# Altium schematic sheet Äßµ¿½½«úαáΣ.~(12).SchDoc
size A4
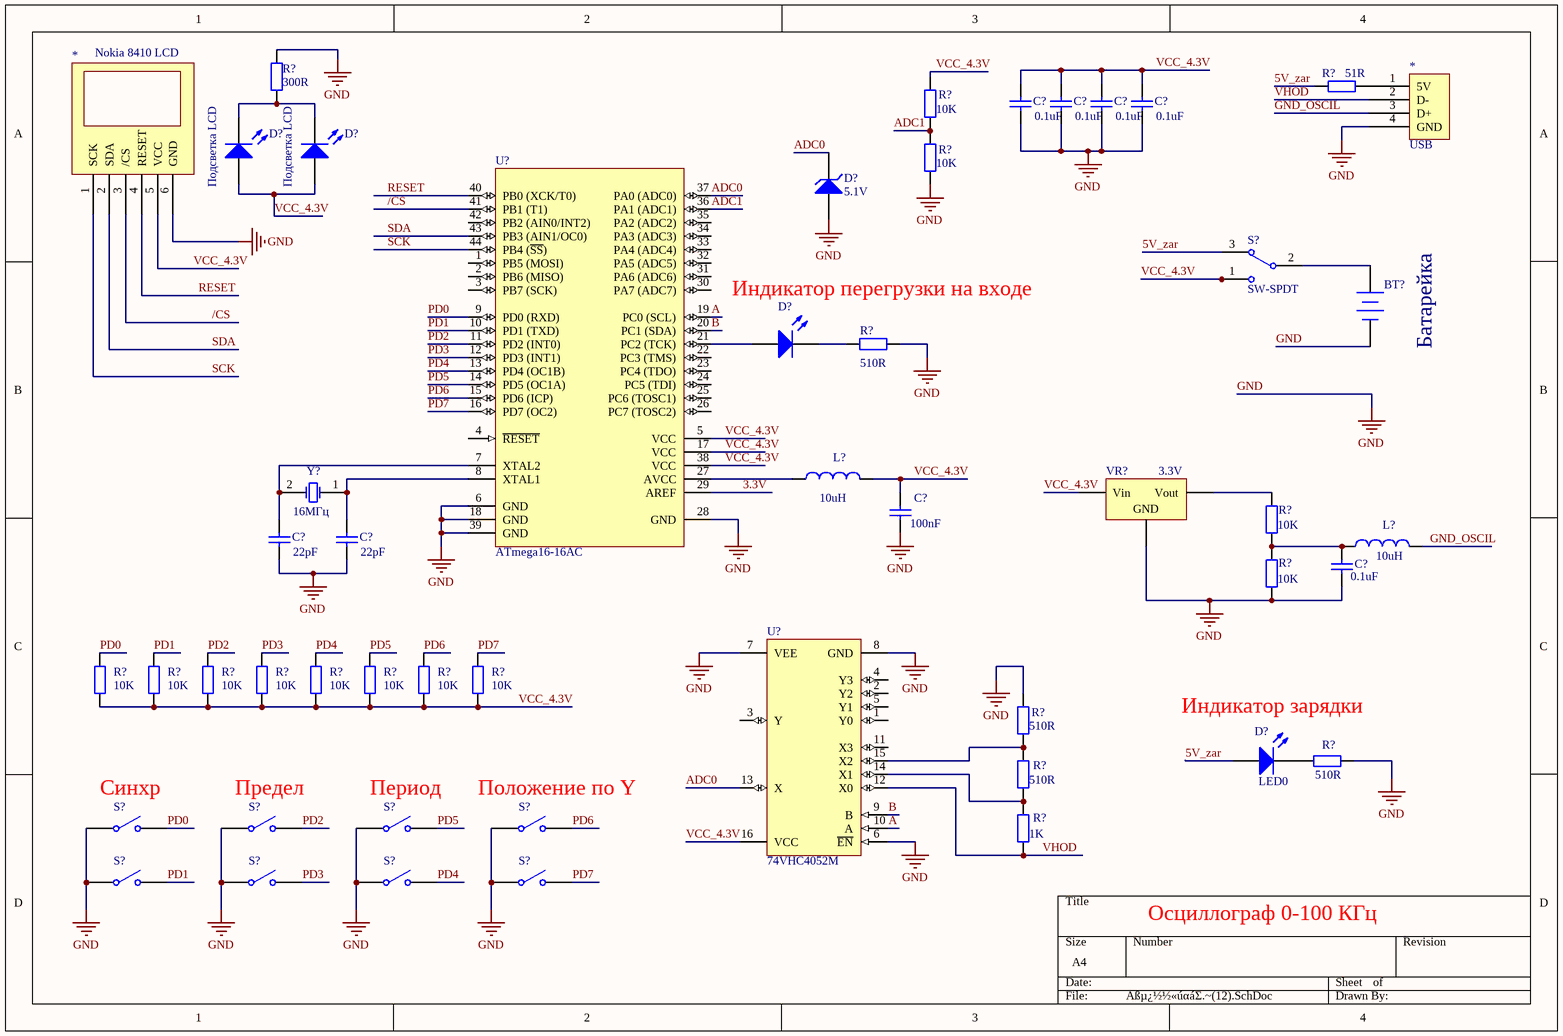
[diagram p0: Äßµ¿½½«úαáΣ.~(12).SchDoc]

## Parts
(Parts that share a designator on the sheet are numbered #1, #2 ... from top to bottom, then left to right.)
*#1  USB
*#2  Nokia 8410 LCD
BT?  Батарейка  [BAT-2]
C?#1  value 0.1uF  [RAD-0.3]  (hidden comment: Cap)
C?#2  value 0.1uF  [RAD-0.3]  (hidden comment: Cap)
C?#3  value 0.1uF  [RAD-0.3]  (hidden comment: Cap)
C?#4  value 0.1uF  [RAD-0.3]  (hidden comment: Cap)
C?#5  value 100nF  [RAD-0.3]  (hidden comment: Cap)
C?#6  value 22pF  [RAD-0.3]  (hidden comment: Cap)
C?#7  value 22pF  [RAD-0.3]  (hidden comment: Cap)
C?#8  value 0.1uF  [RAD-0.3]  (hidden comment: Cap)
D?#1  Подсветка LCD  [LED-0]
D?#2  Подсветка LCD  [LED-0]
D?#3  5.1V  [DIODE-0.7]
D?#4  LED0  [LED-0]  (value not drawn)
D?#5  LED0  [LED-0]
L?#1  value 10uH  [INDC1005AL]  (hidden comment: Inductor)
L?#2  value 10uH  [INDC1005AL]  (hidden comment: Inductor)
R?#1  value 51R  [AXIAL-0.4]  (hidden comment: Res2)
R?#2  value 300R  [AXIAL-0.4]  (hidden comment: Res2)
R?#3  value 10K  [AXIAL-0.4]  (hidden comment: Res2)
R?#4  value 10K  [AXIAL-0.4]  (hidden comment: Res2)
R?#5  value 510R  [AXIAL-0.4]  (hidden comment: Res2)
R?#6  value 10K  [AXIAL-0.4]  (hidden comment: Res2)
R?#7  value 10K  [AXIAL-0.4]  (hidden comment: Res2)
R?#8  value 10K  [AXIAL-0.4]  (hidden comment: Res2)
R?#9  value 10K  [AXIAL-0.4]  (hidden comment: Res2)
R?#10  value 10K  [AXIAL-0.4]  (hidden comment: Res2)
R?#11  value 10K  [AXIAL-0.4]  (hidden comment: Res2)
R?#12  value 10K  [AXIAL-0.4]  (hidden comment: Res2)
R?#13  value 10K  [AXIAL-0.4]  (hidden comment: Res2)
R?#14  value 10K  [AXIAL-0.4]  (hidden comment: Res2)
R?#15  value 10K  [AXIAL-0.4]  (hidden comment: Res2)
R?#16  value 510R  [AXIAL-0.4]  (hidden comment: Res2)
R?#17  value 510R  [AXIAL-0.4]  (hidden comment: Res2)
R?#18  value 510R  [AXIAL-0.4]  (hidden comment: Res2)
R?#19  value 1K  [AXIAL-0.4]  (hidden comment: Res2)
S?#1  SW-SPDT  [TL36WW15050]
S?#2  SW-SPST  [SPST-2]  (value not drawn)
S?#3  SW-SPST  [SPST-2]  (value not drawn)
S?#4  SW-SPST  [SPST-2]  (value not drawn)
S?#5  SW-SPST  [SPST-2]  (value not drawn)
S?#6  SW-SPST  [SPST-2]  (value not drawn)
S?#7  SW-SPST  [SPST-2]  (value not drawn)
S?#8  SW-SPST  [SPST-2]  (value not drawn)
S?#9  SW-SPST  [SPST-2]  (value not drawn)
U?#1  ATmega16-16AC  [44A_N]
U?#2  74VHC4052M  [M16A_N]
VR?  3.3V  [TO254P1510-3_4N]
Y?  16МГц  [BCY-W2/D3.1]

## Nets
GND: *#1.4(GND) *#2.6(GND) BT?.2(-) C?#1.1 C?#2.1 C?#3.1 C?#4.1 C?#5.1 C?#6.1 C?#7.1 C?#8.1 D?#3.1(A) R?#2.2 R?#4.1 R?#5.2 R?#7.2 R?#16.2 R?#17.2 S?#2.1(COMMON) S?#3.1(COMMON) S?#4.1(COMMON) S?#5.1(COMMON) S?#6.1(COMMON) S?#7.1(COMMON) S?#8.1(COMMON) S?#9.1(COMMON) U?#1.6(GND) U?#1.18(GND) U?#1.28(GND) U?#1.39(GND) U?#2.6(~{EN}) U?#2.7(VEE) U?#2.8(GND) VR?.2(GND)
3.3V: U?#1.29(AREF)
5V_zar: D?#5.1(A) R?#1.1 S?#1.3
/CS: *#2.3(/CS) U?#1.41(PB1_(T1))
A: U?#1.19(PC0_(SCL)) U?#2.10(A)
ADC0: D?#3.2(K) U?#1.37(PA0_(ADC0)) U?#2.13(X)
ADC1: R?#3.1 R?#4.2 U?#1.36(PA1_(ADC1))
B: U?#1.20(PC1_(SDA)) U?#2.9(B)
GND_OSCIL: *#1.3(D+) L?#2.2
PD0: R?#8.2 S?#2.2(NO) U?#1.9(PD0_(RXD))
PD1: R?#9.2 S?#6.2(NO) U?#1.10(PD1_(TXD))
PD2: R?#10.2 S?#3.2(NO) U?#1.11(PD2_(INT0))
PD3: R?#11.2 S?#7.2(NO) U?#1.12(PD3_(INT1))
PD4: R?#12.2 S?#8.2(NO) U?#1.13(PD4_(OC1B))
PD5: R?#13.2 S?#4.2(NO) U?#1.14(PD5_(OC1A))
PD6: R?#14.2 S?#5.2(NO) U?#1.15(PD6_(ICP))
PD7: R?#15.2 S?#9.2(NO) U?#1.16(PD7_(OC2))
RESET: *#2.4(RESET) U?#1.40(PB0_(XCK/T0))
SCK: *#2.1(SCK) U?#1.44(PB4_(~{SS}))
SDA: *#2.2(SDA) U?#1.43(PB3_(AIN1/OC0))
VCC_4.3V: *#2.5(VCC) C?#1.2 C?#2.2 C?#3.2 C?#4.2 C?#5.2 D?#1.1(A) D?#2.1(A) L?#1.2 R?#3.2 R?#8.1 R?#9.1 R?#10.1 R?#11.1 R?#12.1 R?#13.1 R?#14.1 R?#15.1 S?#1.1 U?#1.5(VCC) U?#1.17(VCC) U?#1.38(VCC) U?#2.16(VCC) VR?.1(Vin)
VHOD: *#1.2(D-) R?#19.1 U?#2.12(X0)
Net*#1_1: *#1.1(5V) R?#1.2
NetBT?_1: BT?.1(+) S?#1.2
NetC?#6_2: C?#6.2 U?#1.7(XTAL2) Y?.2(OSC2)
NetC?#7_2: C?#7.2 U?#1.8(XTAL1) Y?.1(OSC1)
NetC?#8_2: C?#8.2 L?#2.1 R?#6.1 R?#7.1
NetD?#1_2: D?#1.2(K) D?#2.2(K) R?#2.1
NetD?#4_1: D?#4.1(A) U?#1.21(PC2_(TCK))
NetD?#4_2: D?#4.2(K) R?#5.1
NetD?#5_2: D?#5.2(K) R?#17.1
NetL?#1_1: L?#1.1 U?#1.27(AVCC)
NetR?#6_2: R?#6.2 VR?.3(Vout)
NetR?#16_1: R?#16.1 R?#18.2 U?#2.15(X2)
NetR?#18_1: R?#18.1 R?#19.2 U?#2.14(X1)

Not connected (* = marked no-connect by the designer): U?#1 1(PB5_(MOSI)) 2(PB6_(MISO)) 3(PB7_(SCK)) 4(~{RESET}) 22(PC3_(TMS)) 23(PC4_(TDO)) 24(PC5_(TDI)) 25(PC6_(TOSC1)) 26(PC7_(TOSC2)) 30(PA7_(ADC7)) 31(PA6_(ADC6)) 32(PA5_(ADC5)) 33(PA4_(ADC4)) 34(PA3_(ADC3)) 35(PA2_(ADC2)) 42(PB2_(AIN0/INT2)); U?#2 1(Y0) 2(Y2) 3(Y) 4(Y3) 5(Y1) 11(X3)

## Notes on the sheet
- Индикатор перегрузки на входе
- Индикатор зарядки
- (near S?#2) Синхр
- (near S?#3) Предел
- (near S?#4) Период
- (near S?#5) Положение по Y
- Осциллограф 0-100 КГц

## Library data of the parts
*#2 = Component_1
BT? = Battery: Multicell Battery
C?#1-C?#8 = Cap: Capacitor
D?#1 D?#2 D?#4 D?#5 = LED0: Typical INFRARED GaAs LED
D?#3 = D Zener: Zener Diode
L?#1 L?#2 = Inductor: Code_IEC: 1005
R?#1-R?#19 = Res2: Resistor
S?#1 = SW-SPDT: SPDT Subminiature Toggle Switch, Right Angle Mounting, Vertical Actuation
S?#2-S?#9 = SW-SPST: Single-Pole, Single-Throw Switch
U?#1 = ATmega16-16AC: 8-Bit AVR Microcontroller with 16K Bytes of In-System Programmable Flash Memory
U?#2 = 74VHC4052M: Dual 4-Channel Analog Multiplexer
VR? = Volt Reg: Voltage Regulator
Y? = XTAL: Crystal Oscillator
